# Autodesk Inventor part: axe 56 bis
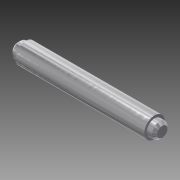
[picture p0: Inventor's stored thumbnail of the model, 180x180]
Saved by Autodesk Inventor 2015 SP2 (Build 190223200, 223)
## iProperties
Created: 2015-08
Part Number: axe 56 bis
Material: Générique
Document SubType Name: Modeling
Designer: Dominique
Density: 1 g/cm^3
Appearance: Usiné - Aluminium
Author: Dominique
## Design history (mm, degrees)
sketch "Esquisse1"
  geometry: L1 (0, 0)-(56, 0); L2 (56, 0)-(56, 3); L3 (53, 4)-(3, 4); L4 (0, 3)-(0, 0); L5 (3, 4)-(3, 3); L6 (3, 3)-(0, 3); L7 (53, 4)-(53, 3); L8 (53, 3)-(56, 3)
  constraints: 16 end point, 2 parallel, 1 horizontal, 1 perpendicular
revolve "Révolution1" sketch "Esquisse1" stored, may be unused: angle "d6" = 90 deg
chamfer "Chanfrein1" distance "d7" = 1; stored, may be unused: second distance "d8" = 2, angle "d9" = 45 deg
node "Solide1"
